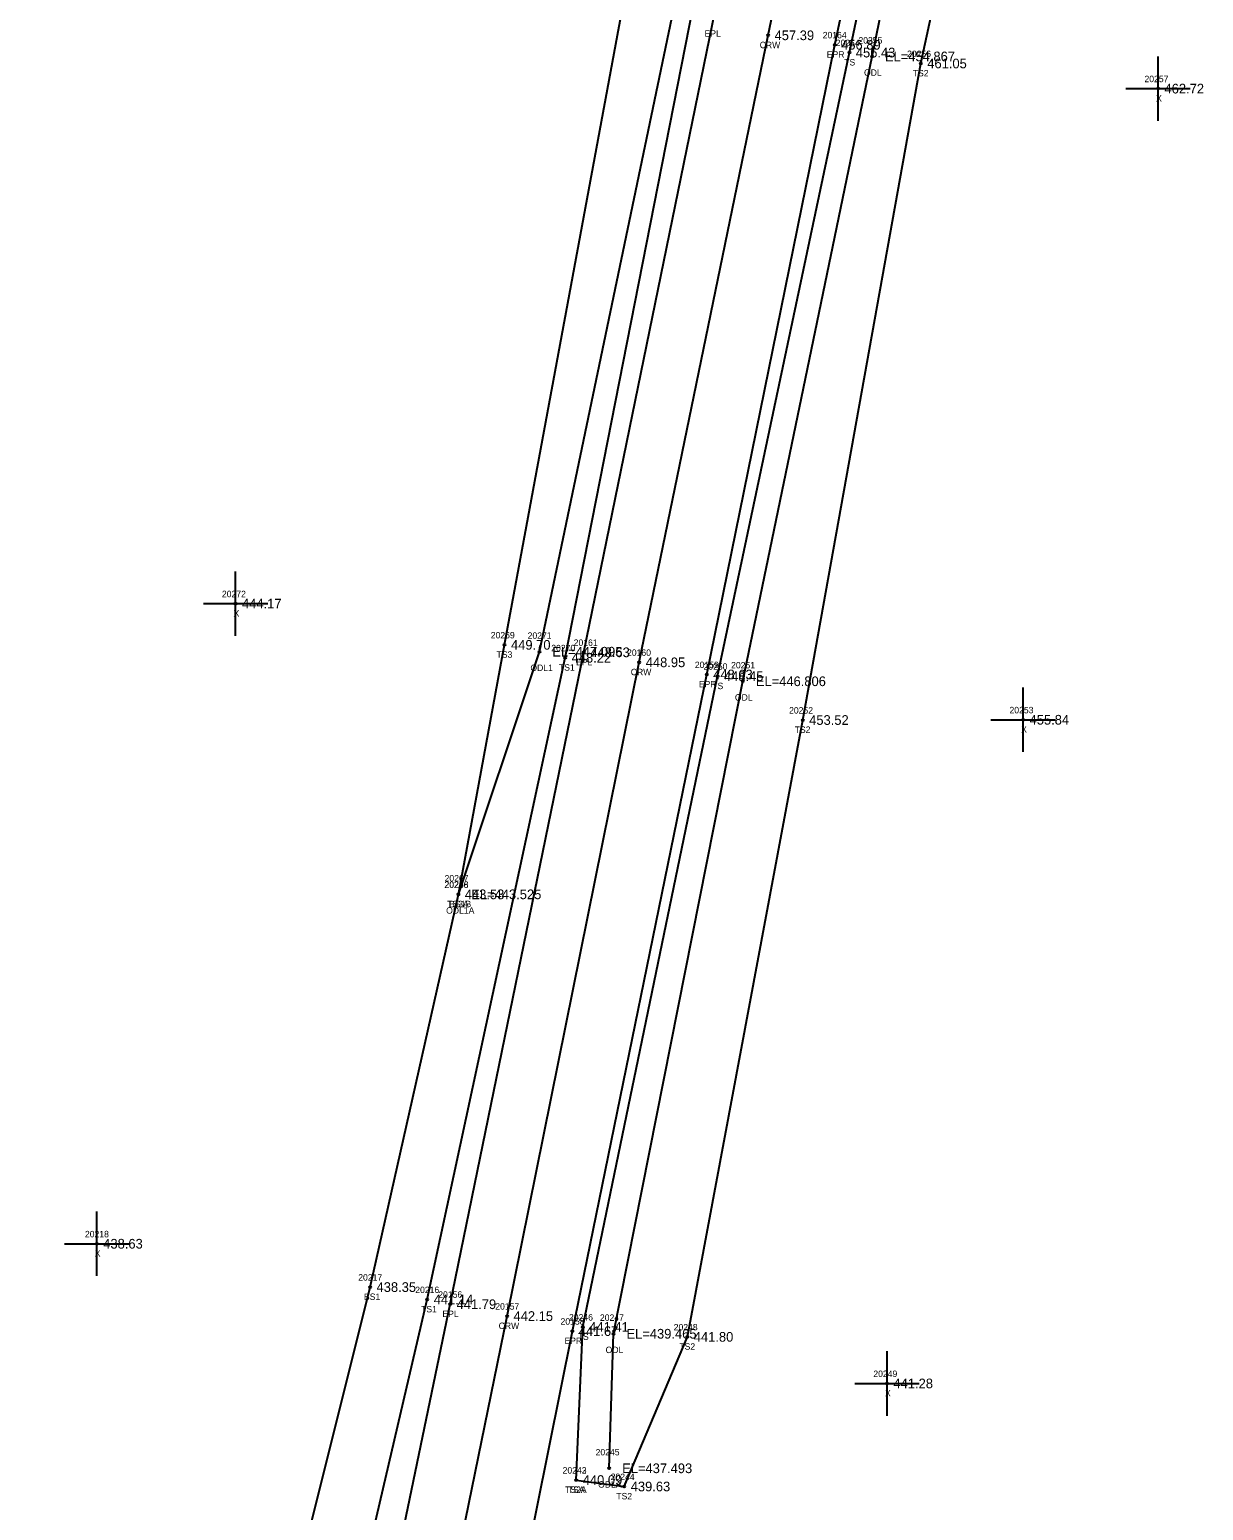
# Model space of a CAD drawing. Extents: x 1755707 to 1756750, y 975854 to 977363.
# Drawn here: x 1756200.1 to 1756382.3, y 976912.7 to 977142.4 of the extents above; entities that cross this region are included whole.
import ezdxf

# ---------------------------------------------------------------- set-up
doc = ezdxf.new("R2010")
doc.units = 0
for name, color, linetype in [('RD_DTM_BkLn1', 7, 'Continuous'), ('RD_DTM_BkLn2', 7, 'Continuous'), ('RD_DTM_BkLn_txCode', 7, 'Continuous'), ('RD_EX_H2O', 7, 'Continuous'), ('RD_EX_H2O_txCode', 7, 'Continuous'), ('RD_EX_Misc', 7, 'Continuous'), ('RD_EX_Misc_txCode', 7, 'Continuous'), ('RD_EX_Road', 7, 'Continuous'), ('RD_EX_Road_txCode', 7, 'Continuous'), ('RD_EX_TX_H2O_ELEV', 7, 'Continuous'), ('RD_EX_TX_Misc_ELEV', 7, 'Continuous'), ('RD_EX_TX_Road_ELEV', 7, 'Continuous'), ('RD_HC_Survey_ELEV', 7, 'Continuous'), ('RD_HC_Survey_txCode', 7, 'Continuous'), ('RD_SMD_Locator', 7, 'Continuous')]:
    doc.layers.add(name, color=color, linetype=linetype)

msp = doc.modelspace()

# ---------------------------------------------------------------- linework, layer by layer
at = {"layer": 'RD_DTM_BkLn1'}
msp.add_lwpolyline([(1756212.24, 976646.92), (1756233.31, 976744.58), (1756253.87, 976843.36), (1756274.18, 976942.87), (1756294.7, 977044.28), (1756314.7, 977141.54), (1756335.65, 977241.96), (1756357.9, 977342.03)], dxfattribs=at)
at = {"layer": 'RD_DTM_BkLn2'}
for points in [[(1756101.82, 976704.9), (1756150.92, 976716.16), (1756211.72, 976728.04), (1756216.23, 976737.89), (1756238.86, 976847.03), (1756261.79, 976945.44), (1756283.19, 977044.99), (1756303.06, 977145.95), (1756325.46, 977245.55), (1756346.55, 977344.09)], [(1756266.62, 977008.29), (1756273.79, 977046.99), (1756292.52, 977148.02), (1756315.03, 977249.35), (1756336.62, 977344.78)], [(1756284.92, 976917.44), (1756285.93, 976941.18), (1756306.83, 977042.12), (1756327.31, 977138.86), (1756348.69, 977240.29), (1756370.45, 977339.68)], [(1756284.92, 976917.44), (1756292.37, 976916.44), (1756302.16, 976939.65), (1756320.07, 977035.33), (1756338.4, 977137.17), (1756360.87, 977240.74), (1756378.56, 977338.18)], [(1756101.82, 976704.9), (1756144.73, 976723.58), (1756149.68, 976727.6), (1756152.89, 976726.7), (1756204.3, 976738.63), (1756228.54, 976849.91), (1756252.92, 976947.37), (1756266.62, 977008.29)]]:
    msp.add_lwpolyline(points, dxfattribs=at)
at = {"layer": 'RD_EX_H2O'}
for points in [[(1756266.62, 977008.29), (1756279.21, 977045.93), (1756300.28, 977146.66), (1756321.97, 977246.56), (1756343.71, 977344.18)], [(1756290.04, 976919.26), (1756290.71, 976940.13), (1756310.79, 977041.34), (1756330.83, 977138.26), (1756351.52, 977239.88), (1756373.82, 977339.31)]]:
    msp.add_lwpolyline(points, dxfattribs=at)
at = {"layer": 'RD_EX_Misc'}
for p, q in [((1756375.22, 977128.27), (1756375.22, 977138.27)), ((1756370.22, 977133.27), (1756380.22, 977133.27)), ((1756232.04, 977048.38), (1756232.04, 977058.38)), ((1756227.04, 977053.38), (1756237.04, 977053.38)), ((1756354.28, 977030.37), (1756354.28, 977040.37)), ((1756349.28, 977035.37), (1756359.28, 977035.37)), ((1756210.5, 976949.09), (1756210.5, 976959.09)), ((1756205.5, 976954.09), (1756215.5, 976954.09)), ((1756333.15, 976927.42), (1756333.15, 976937.42)), ((1756328.15, 976932.42), (1756338.15, 976932.42))]:
    msp.add_line(p, q, dxfattribs=at)
at = {"layer": 'RD_EX_Road'}
for points in [[(1756212.24, 976646.92), (1756202.87, 976648.96), (1756215.01, 976705.04), (1756220.09, 976730.75), (1756223.91, 976746.46), (1756244.6, 976844.81), (1756265.35, 976944.71), (1756286.1, 977045.83), (1756306.04, 977143.32), (1756326.71, 977243.79), (1756348.97, 977343.58)], [(1756212.24, 976646.92), (1756220.86, 976645.39), (1756242.73, 976741.74), (1756264.15, 976840.28), (1756284.31, 976940.54), (1756305.17, 977042.39), (1756325.03, 977140.07), (1756346.16, 977239.41), (1756368.47, 977341.2)]]:
    msp.add_lwpolyline(points, dxfattribs=at)
at = {"layer": 'RD_SMD_Locator'}
for centre in [(1756314.7, 977141.54), (1756325.03, 977140.07), (1756327.31, 977138.86), (1756330.83, 977138.26), (1756338.4, 977137.17), (1756375.22, 977133.27), (1756232.04, 977053.38), (1756273.79, 977046.99), (1756279.21, 977045.93), (1756286.1, 977045.83), (1756283.19, 977044.99), (1756294.7, 977044.28), (1756305.17, 977042.39), (1756306.83, 977042.12), (1756310.79, 977041.34), (1756320.07, 977035.33), (1756354.28, 977035.37), (1756266.62, 977008.29), (1756266.62, 977008.29), (1756266.62, 977008.29), (1756210.5, 976954.09), (1756252.92, 976947.37), (1756261.79, 976945.44), (1756265.35, 976944.71), (1756274.18, 976942.87), (1756284.31, 976940.54), (1756285.93, 976941.18), (1756290.71, 976940.13), (1756302.16, 976939.65), (1756333.15, 976932.42), (1756290.04, 976919.26), (1756284.92, 976917.44), (1756284.92, 976917.44), (1756292.37, 976916.44)]:
    msp.add_circle(centre, 0.15, dxfattribs=at)

# ---------------------------------------------------------------- texts
at = {"layer": 'RD_DTM_BkLn_txCode'}
for s, p in [('20254', (1756325.19, 977139.86)), ('TS', (1756326.51, 977136.86)), ('20256', (1756336.26, 977138.17)), ('TS2', (1756337.15, 977135.17)), ('20269', (1756271.65, 977047.99)), ('TS3', (1756272.55, 977044.99)), ('20270', (1756281.04, 977045.99)), ('TS1', (1756282.23, 977042.99)), ('20250', (1756304.67, 977043.12)), ('TS', (1756306.03, 977040.12)), ('20252', (1756317.95, 977036.33)), ('TS2', (1756318.82, 977033.33)), ('20266', (1756264.45, 977009.29)), ('20268', (1756264.48, 977009.29)), ('TS3A', (1756264.89, 977006.29)), ('BS1B', (1756265.2, 977006.29)), ('20217', (1756251.08, 976948.37)), ('20216', (1756259.93, 976946.44)), ('BS1', (1756251.97, 976945.37)), ('TS1', (1756260.83, 976943.44)), ('20246', (1756283.79, 976942.18)), ('TS', (1756285.14, 976939.18)), ('20248', (1756300.04, 976940.65)), ('TS2', (1756300.92, 976937.65)), ('20242', (1756282.8, 976918.44)), ('20243', (1756282.8, 976918.44)), ('20244', (1756290.26, 976917.44)), ('TS2A', (1756283.18, 976915.44)), ('TSA', (1756283.63, 976915.44)), ('TS2', (1756291.13, 976914.44))]:
    msp.add_text(s, height=1, dxfattribs=at).set_placement(p)
at = {"layer": 'RD_EX_H2O_txCode'}
for s, p in [('20255', (1756328.71, 977140.26)), ('ODL', (1756329.58, 977135.26)), ('20271', (1756277.37, 977047.93)), ('ODL1', (1756277.8, 977042.93)), ('20251', (1756308.95, 977043.34)), ('ODL', (1756309.54, 977038.34)), ('20267', (1756264.48, 977010.29)), ('ODL1A', (1756264.72, 977005.29)), ('20247', (1756288.59, 976942.13)), ('ODL', (1756289.47, 976937.13)), ('20245', (1756287.92, 976921.26)), ('ODLA', (1756288.31, 976916.26))]:
    msp.add_text(s, height=1, dxfattribs=at).set_placement(p)
at = {"layer": 'RD_EX_Misc_txCode'}
for s, p in [('20257', (1756373.11, 977134.27)), ('X', (1756374.91, 977131.27)), ('20272', (1756229.92, 977054.38)), ('X', (1756231.72, 977051.38)), ('20253', (1756352.16, 977036.37)), ('X', (1756353.97, 977033.37)), ('20218', (1756208.66, 976955.09)), ('X', (1756210.18, 976952.09)), ('20249', (1756331.03, 976933.42)), ('X', (1756332.84, 976930.42))]:
    msp.add_text(s, height=1, dxfattribs=at).set_placement(p)
at = {"layer": 'RD_EX_Road_txCode'}
for s, p in [('EPL', (1756304.83, 977141.32)), ('20164', (1756323.17, 977141.07)), ('EPR', (1756323.8, 977138.07)), ('20161', (1756284.52, 977046.83)), ('EPL', (1756284.89, 977043.83)), ('20159', (1756303.33, 977043.39)), ('EPR', (1756303.94, 977040.39)), ('20156', (1756263.5, 976945.71)), ('EPL', (1756264.15, 976942.71)), ('20158', (1756282.48, 976941.54)), ('EPR', (1756283.09, 976938.54))]:
    msp.add_text(s, height=1, dxfattribs=at).set_placement(p)
at = {"layer": 'RD_EX_TX_H2O_ELEV'}
for s, p in [('EL=454.867', (1756332.83, 977137.51)), ('EL=447.095', (1756281.21, 977045.18)), ('EL=446.806', (1756312.79, 977040.59)), ('EL=443.525', (1756268.62, 977007.54)), ('EL=439.465', (1756292.71, 976939.38)), ('EL=437.493', (1756292.04, 976918.51))]:
    msp.add_text(s, height=1.5, dxfattribs=at).set_placement(p)
at = {"layer": 'RD_EX_TX_Misc_ELEV'}
for s, p in [('456.43', (1756328.31, 977138.11)), ('461.05', (1756339.4, 977136.42)), ('462.72', (1756376.22, 977132.52)), ('444.17', (1756233.04, 977052.63)), ('449.70', (1756274.79, 977046.24)), ('448.22', (1756284.19, 977044.24)), ('448.45', (1756307.83, 977041.37)), ('453.52', (1756321.07, 977034.58)), ('455.84', (1756355.28, 977034.62)), ('443.53', (1756267.62, 977007.54)), ('443.53', (1756267.62, 977007.54)), ('438.63', (1756211.5, 976953.34)), ('438.35', (1756253.92, 976946.62)), ('441.14', (1756262.79, 976944.69)), ('441.41', (1756286.93, 976940.43)), ('441.80', (1756303.16, 976938.9)), ('441.28', (1756334.15, 976931.67)), ('440.09', (1756285.92, 976916.69)), ('440.09', (1756285.92, 976916.69)), ('439.63', (1756293.37, 976915.69))]:
    msp.add_text(s, height=1.5, dxfattribs=at).set_placement(p)
at = {"layer": 'RD_EX_TX_Road_ELEV'}
for s, p in [('456.89', (1756326.03, 977139.32)), ('448.63', (1756287.1, 977045.08)), ('448.63', (1756306.17, 977041.64)), ('441.79', (1756266.35, 976943.96)), ('441.67', (1756285.31, 976939.79))]:
    msp.add_text(s, height=1.5, dxfattribs=at).set_placement(p)
at = {"layer": 'RD_HC_Survey_ELEV'}
for s, p in [('457.39', (1756315.7, 977140.79)), ('448.95', (1756295.7, 977043.53)), ('442.15', (1756275.18, 976942.12))]:
    msp.add_text(s, height=1.5, dxfattribs=at).set_placement(p)
at = {"layer": 'RD_HC_Survey_txCode'}
for s, p in [('CRW', (1756313.39, 977139.54)), ('20160', (1756292.8, 977045.28)), ('CRW', (1756293.38, 977042.28)), ('20157', (1756272.35, 976943.87)), ('CRW', (1756272.87, 976940.87))]:
    msp.add_text(s, height=1, dxfattribs=at).set_placement(p)

doc.saveas('drawing.dxf')
